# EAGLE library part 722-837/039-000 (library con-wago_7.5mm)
Serie 722, Federleiste mit Verriegelungsklinken / Series 722, Female connector with locking levers Polzahl / Pole No.: 7 Farbe / Color: lichtgrau / light gray Stand: 01.01.2012. Die jeweils aktuellen Daten zu diesem Artikel finden Sie in unserem Produktkatalog, den Sie unter www.wago.com einsehen können. As of: 01/01/2012. Please find the newest data for this article in our product catalogue, which can be viewed under www.wago.com.
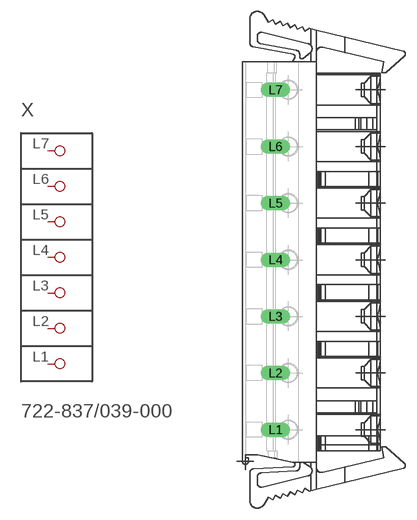
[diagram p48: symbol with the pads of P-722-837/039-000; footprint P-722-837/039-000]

Designator prefix X

## 722-837/039-000  [P-722-837/039-000]
L1  P1
L2  P2
L3  P3
L4  P4
L5  P5
L6  P6
L7  P7

## Footprint P-722-837/039-000 (pad centres in mm)
drill 1.3 long: L1 -6.054,-22.5; L2 -6.054,-15; L3 -6.054,-7.5; L4 -6.054,0; L5 -6.054,7.5; L6 -6.054,15; L7 -6.054,22.5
